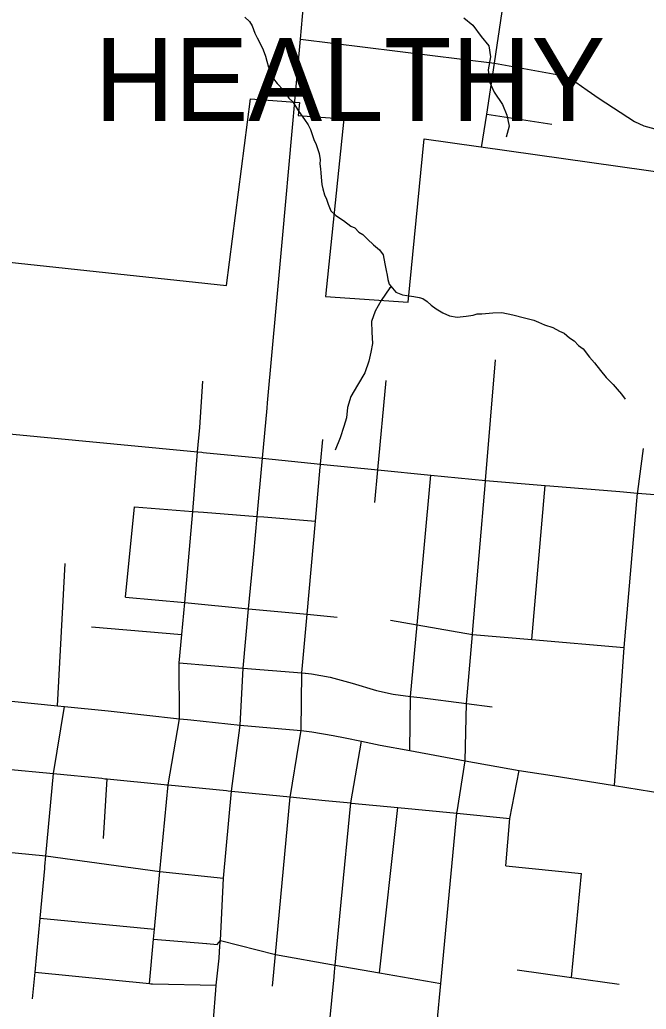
# Model space of a CAD drawing. Extents: x 0 to 69.5, y -4.5 to 22.
# Drawn here: x 6.256 to 6.973, y 15.927 to 17.057 of the extents above; entities that cross this region are included whole.
import ezdxf

# ---------------------------------------------------------------- set-up
doc = ezdxf.new("R2010")
doc.units = 0
for name, color, linetype in [('GM_X_City_Street', 7, 'Continuous'), ('GM_X_Corporation', 7, 'Continuous'), ('GM_X_Corporation_Text', 7, 'Continuous'), ('GM_X_County_Road', 7, 'Continuous'), ('GM_X_Minor_River', 7, 'Continuous'), ('GM_X_Township_Subdivision', 7, 'Continuous'), ('GM_X_US_Route', 7, 'Continuous')]:
    doc.layers.add(name, color=color, linetype=linetype)

msp = doc.modelspace()

# ---------------------------------------------------------------- linework, layer by layer
at = {"layer": 'GM_X_City_Street'}
for points in [[(6.7887, 16.5295), (6.7888, 16.5307), (6.8004, 16.6687)], [(6.4045, 15.9559), (6.4093, 16.0066), (6.4104, 16.0183), (6.4166, 16.084), (6.4259, 16.183), (6.439, 16.2586), (6.4387, 16.3225), (6.4416, 16.3547), (6.4449, 16.3912), (6.4542, 16.4954), (6.4597, 16.5634), (6.462, 16.5914), (6.4658, 16.6441)], [(6.6623, 16.5056), (6.6658, 16.543), (6.6752, 16.6452)], [(6.0405, 16.6037), (6.4597, 16.5634), (6.4644, 16.563), (6.4661, 16.5628)], [(6.5999, 16.5461), (6.6, 16.5474), (6.6002, 16.5496), (6.6027, 16.5776)], [(6.4661, 16.5628), (6.5338, 16.5563), (6.6002, 16.5496), (6.6658, 16.543), (6.7262, 16.537), (6.7888, 16.5307), (6.857, 16.5251), (6.8624, 16.5247), (6.9426, 16.5182)], [(6.963, 16.5182), (6.9696, 16.5673)], [(6.5754, 16.2294), (6.578, 16.245), (6.5788, 16.3109), (6.5851, 16.3779), (6.5945, 16.4844), (6.5999, 16.5461)], [(6.7022, 16.2224), (6.7032, 16.2841), (6.7106, 16.3658), (6.7262, 16.537)], [(6.7744, 16.3605), (6.7887, 16.5295), (6.7887, 16.5295)], [(6.8418, 16.349), (6.857, 16.5251)], [(6.9364, 16.1823), (6.9475, 16.34), (6.9628, 16.5165), (6.963, 16.5175), (6.963, 16.5182)], [(6.9426, 16.5182), (6.9628, 16.5165), (7.0315, 16.511), (7.0972, 16.503), (7.1529, 16.4963)], [(6.3772, 16.3975), (6.3874, 16.5007)], [(6.3874, 16.5007), (6.4542, 16.4954), (6.4663, 16.4945), (6.4663, 16.4945)], [(6.4663, 16.4945), (6.5277, 16.4897), (6.5353, 16.4891)], [(6.5353, 16.4891), (6.5353, 16.4891), (6.5945, 16.4844)], [(6.2994, 16.2734), (6.3081, 16.4359)], [(6.3772, 16.3975), (6.4449, 16.3912), (6.518, 16.3843), (6.5851, 16.3779), (6.6192, 16.3747)], [(6.6803, 16.3711), (6.7106, 16.3658), (6.7739, 16.3547), (6.8418, 16.349), (6.9475, 16.34)], [(6.3384, 16.3634), (6.4416, 16.3547)], [(6.7563, 16.1521), (6.7657, 16.2103), (6.7672, 16.2758), (6.7739, 16.3547), (6.7744, 16.3605), (6.7744, 16.3605)], [(6.4387, 16.3225), (6.5108, 16.3165), (6.5109, 16.3165)], [(6.5109, 16.3165), (6.5117, 16.3165), (6.5788, 16.3109), (6.5828, 16.3106), (6.5831, 16.3106)], [(5.9866, 16.3066), (6.0139, 16.3035), (6.1281, 16.2913), (6.2279, 16.2806), (6.2994, 16.2734), (6.3075, 16.2727), (6.3572, 16.2675), (6.439, 16.2586), (6.4481, 16.2577)], [(6.5831, 16.3106), (6.59, 16.31), (6.6112, 16.3061), (6.6365, 16.2991), (6.6641, 16.2909), (6.6834, 16.2867), (6.7032, 16.2841), (6.7142, 16.2827), (6.7143, 16.2827)], [(6.7143, 16.2827), (6.7672, 16.2758), (6.7964, 16.272)], [(6.285, 16.0898), (6.2862, 16.1018), (6.2949, 16.1959), (6.3075, 16.2727)], [(6.4481, 16.2577), (6.452, 16.2573), (6.5082, 16.2512), (6.5734, 16.2454)], [(6.5734, 16.2454), (6.578, 16.245), (6.5901, 16.2435), (6.6146, 16.2395), (6.6283, 16.2369), (6.647, 16.2328), (6.6684, 16.2283), (6.7022, 16.2224), (6.7657, 16.2103), (6.8275, 16.1996), (6.8652, 16.1938), (6.9364, 16.1823), (7.0493, 16.1641), (7.0869, 16.158), (7.13, 16.1509), (7.1731, 16.1436), (7.1741, 16.1434)], [(6.5454, 15.953), (6.5488, 15.9891), (6.5656, 16.1692), (6.5657, 16.1707), (6.5754, 16.2294)], [(6.6157, 15.9635), (6.6163, 15.9695), (6.617, 15.9772), (6.6239, 16.0489), (6.635, 16.1624), (6.647, 16.2328)], [(6.213, 16.2039), (6.2382, 16.2015), (6.2949, 16.1959), (6.3501, 16.1905)], [(6.3501, 16.1905), (6.3537, 16.1901), (6.3563, 16.1899), (6.4213, 16.1835)], [(6.3522, 16.1218), (6.3563, 16.1899)], [(6.8122, 16.0904), (6.8167, 16.1447), (6.8275, 16.1996)], [(6.4213, 16.1835), (6.4241, 16.1832), (6.4259, 16.183), (6.4925, 16.1765)], [(6.4925, 16.1765), (6.4945, 16.1763), (6.4985, 16.1759), (6.5656, 16.1692), (6.6055, 16.1653), (6.635, 16.1624)], [(6.635, 16.1624), (6.6357, 16.1623), (6.6887, 16.1571), (6.7561, 16.1506), (6.8167, 16.1447)], [(6.6677, 15.9684), (6.6887, 16.1571)], [(6.7292, 15.8641), (6.7295, 15.8678), (6.7378, 15.9562), (6.7561, 16.1506), (6.7562, 16.1518), (6.7563, 16.1521)], [(6.2352, 16.1067), (6.2354, 16.1067), (6.2862, 16.1018), (6.4166, 16.084), (6.4891, 16.0765)], [(6.271, 15.9385), (6.2738, 15.9689), (6.2796, 16.0307), (6.2848, 16.0875), (6.285, 16.0898)], [(6.8122, 16.0904), (6.8986, 16.0817)], [(6.8871, 15.9629), (6.8986, 16.0817)], [(6.2796, 16.0307), (6.4104, 16.0183)], [(6.4093, 16.0066), (6.4699, 16.0017), (6.4701, 16.0017)], [(6.4701, 16.0017), (6.482, 16.0008), (6.4857, 16.0051), (6.5488, 15.9891), (6.617, 15.9772), (6.6677, 15.9684), (6.7378, 15.9562)], [(6.2738, 15.9689), (6.4045, 15.9559), (6.4061, 15.9558), (6.4082, 15.9557)], [(6.6042, 15.8442), (6.6083, 15.8863), (6.6157, 15.9635)], [(6.8252, 15.9715), (6.8871, 15.9629), (6.9415, 15.9553)], [(6.4082, 15.9557), (6.4809, 15.9541)]]:
    msp.add_lwpolyline(points, dxfattribs=at)
at = {"layer": 'GM_X_Corporation'}
msp.add_lwpolyline([(6.1981, 17.0859), (6.1729, 16.7878), (6.4927, 16.7536), (6.5203, 16.9669), (6.5761, 16.9627), (6.5748, 16.9477), (6.6269, 16.944), (6.6059, 16.7411), (6.7005, 16.7344), (6.7188, 16.9212), (7.1642, 16.8585)], dxfattribs=at)
at = {"layer": 'GM_X_County_Road'}
msp.add_lwpolyline([(6.5773, 17.0352), (6.799, 17.0076), (6.8744, 16.994), (6.8855, 16.9906), (6.9051, 16.9769), (6.9189, 16.9674), (6.9593, 16.9408), (6.9699, 16.9359), (7.0092, 16.9255)], dxfattribs=at)
at = {"layer": 'GM_X_Minor_River'}
for points in [[(6.5135, 17.0602), (6.519, 17.0551), (6.5219, 17.0501), (6.5251, 17.042), (6.5277, 17.0366), (6.532, 17.0285), (6.5345, 17.0227), (6.5374, 17.0157), (6.5387, 17.01), (6.5408, 17.0031), (6.5448, 16.9946), (6.5465, 16.9896), (6.5506, 16.9845), (6.558, 16.9767), (6.5638, 16.9678), (6.5686, 16.9635), (6.5737, 16.9545), (6.5781, 16.9487), (6.5818, 16.9433), (6.5862, 16.9371), (6.5887, 16.9317), (6.5926, 16.9205), (6.5951, 16.9147), (6.5969, 16.9101), (6.5986, 16.9044), (6.5996, 16.8971), (6.5994, 16.8925), (6.6, 16.8868), (6.6007, 16.8822), (6.6009, 16.8772), (6.6018, 16.8688), (6.6028, 16.8639), (6.6049, 16.857), (6.6071, 16.8523), (6.6088, 16.8466), (6.612, 16.8389), (6.6176, 16.8334), (6.6266, 16.8278), (6.6348, 16.8215), (6.6393, 16.8194), (6.6441, 16.8144), (6.6486, 16.8119), (6.6538, 16.8065), (6.6608, 16.8002), (6.6675, 16.7943), (6.6719, 16.7888), (6.6739, 16.7785), (6.6752, 16.7708), (6.6762, 16.7655), (6.6772, 16.7605), (6.6786, 16.7551), (6.6863, 16.7461), (6.6939, 16.7429), (6.6988, 16.742), (6.7067, 16.741), (6.7128, 16.7397), (6.7173, 16.7388), (6.7222, 16.7352), (6.7266, 16.7313), (6.7326, 16.727), (6.7401, 16.7222), (6.7476, 16.7189), (6.7563, 16.7175), (6.7666, 16.7184), (6.7746, 16.7197), (6.7792, 16.7211), (6.7845, 16.7213), (6.7971, 16.7225), (6.8074, 16.7226), (6.8199, 16.7199), (6.8335, 16.7165), (6.8441, 16.7139), (6.8493, 16.7115), (6.8561, 16.7087), (6.8659, 16.7057), (6.8734, 16.7013), (6.8786, 16.6993), (6.885, 16.6938), (6.8902, 16.6902), (6.895, 16.6851), (6.9006, 16.6811), (6.9076, 16.6718), (6.9135, 16.6652), (6.9205, 16.6566), (6.9267, 16.6484), (6.9348, 16.6406), (6.9393, 16.6351), (6.9444, 16.6293), (6.9485, 16.6236)], [(6.7639, 17.0593), (6.7743, 17.0511), (6.7839, 17.038), (6.7928, 17.0276), (6.7944, 17.015), (6.7918, 16.9999), (6.7934, 16.9861), (6.7989, 16.9743), (6.8081, 16.9604), (6.8131, 16.9481), (6.8159, 16.9355), (6.8126, 16.9231)], [(6.6812, 16.7521), (6.6796, 16.7511), (6.6694, 16.7365), (6.6626, 16.7241), (6.6585, 16.7125), (6.659, 16.7003), (6.6598, 16.6873), (6.6577, 16.6775), (6.6555, 16.6673), (6.651, 16.6537), (6.6423, 16.6398), (6.6348, 16.6267), (6.6311, 16.6142), (6.6297, 16.6025), (6.6267, 16.5923), (6.6226, 16.5795), (6.617, 16.5655)]]:
    msp.add_lwpolyline(points, dxfattribs=at)
at = {"layer": 'GM_X_Township_Subdivision'}
for points in [[(6.7844, 16.9112), (6.7902, 16.9495), (6.799, 17.0076), (6.8079, 17.0668), (6.8133, 17.1023), (6.8178, 17.1319), (6.8167, 17.1402), (6.8123, 17.154), (6.8001, 17.1868), (6.7932, 17.2092), (6.7932, 17.218), (6.7964, 17.2316), (6.7931, 17.275)], [(6.7902, 16.9495), (6.8648, 16.938)]]:
    msp.add_lwpolyline(points, dxfattribs=at)
at = {"layer": 'GM_X_US_Route'}
for points in [[(6.5713, 16.9682), (6.5773, 17.0352), (6.5796, 17.0608), (6.5848, 17.1183), (6.5857, 17.1275)], [(6.5686, 16.9383), (6.5705, 16.9598), (6.5713, 16.9682)], [(6.5396, 16.6197), (6.5499, 16.732), (6.5568, 16.8072), (6.5679, 16.93), (6.5686, 16.9383)], [(6.4852, 15.999), (6.4857, 16.0051), (6.4891, 16.0765), (6.4985, 16.1759), (6.5082, 16.2512), (6.5117, 16.3165), (6.518, 16.3843), (6.5238, 16.4471), (6.5277, 16.4897), (6.5338, 16.5563), (6.5391, 16.6133), (6.5396, 16.6197)], [(6.4804, 15.9485), (6.4809, 15.9541), (6.4841, 15.985), (6.4852, 15.999)], [(6.4766, 15.898), (6.4779, 15.9151), (6.4804, 15.9485)]]:
    msp.add_lwpolyline(points, dxfattribs=at)

# ---------------------------------------------------------------- texts
at = {"layer": 'GM_X_Corporation_Text'}
msp.add_text('HEALTHY', height=0.0947, rotation=0, dxfattribs=at).set_placement((6.3417, 16.9415))

doc.saveas('drawing.dxf')
